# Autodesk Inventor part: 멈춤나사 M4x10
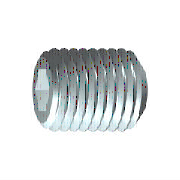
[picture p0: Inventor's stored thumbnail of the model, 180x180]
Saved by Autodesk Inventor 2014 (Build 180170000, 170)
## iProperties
Created: 2012-02
Part Number: 멈춤나사 M4x10
Material: 강철, 연강
Description: 6각 소켓 머리 없는 멈춤 나사
Document SubType Name: Modeling
Standard: KS B 1028
Designer: mduedu
Standards Organization: KS
Language: ko-KR
Size Designation: 납작점M4x10
Categories: <MemberInstance><Categories><Category DisplayName="조임쇠" InternalName="e4da775c-781d-43d5-af7c-5136215cf5a6" Mnemonic="FSTN"><Category DisplayName="볼트" InternalN
Density: 1 g/cm^3
Appearance: 강철
IsCustomPart: 1
Author: mduedu
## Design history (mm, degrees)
sketch "스케치1"
  geometry: L1 (0, 0)-(6.833, 0); L2 (10, 1.155)-(10, 2); L3 (10, 2)-(0, 2); L4 (10, 1.155)-(7.5, 1.155); L5 (7.5, 1.155)-(6.833, 0); L6 (0, -0.4)-(0, 2.4) reference; L7 (0, 2)-(0, 0)
  constraints: 13 end point, 3 parallel, 1 collinear, 1 perpendicular, 1 point on line
  dimensions: "d0" = 2.5 distance of L2.start L4.end (= INTI); "d1" = 60 deg angle of L5 L1; "d2" = 4 diameter of L3 L1 (= NND); "d3" = 2.3094 diameter of L4 L1 (= 1.1547 x SW); "d5" = 10 distance from line of L2 L3.end (= NLG)
revolve "본체" sketch "스케치1" stored, may be unused: angle "d6" = 90 deg
sketch "스케치2"
  geometry: L1 (-0.577, 1)-(0.577, 1); L2 (0.577, 1)-(1.155, 0); L3 (1.155, 0)-(0.577, -1); L4 (0.577, -1)-(-0.577, -1); L5 (-0.577, -1)-(-1.155, 0); L6 (-1.155, 0)-(-0.577, 1); A1 r 1.155 centre (0, 0) between (-0.577, 1) and (0.577, 1) reference; 2 further points
  constraints: 12 end point, 2 point on circle, 1 coincident, 1 horizontal, 11 other
extrude "슬롯" join sketch "스케치2" taper "d9" = 0 deg; stored distance "d21" = 10
workaxis "Work Axis1"
workplane "Work Plane1"
body "Solid1"
chamfer "모따기1" distance "d7" = 0.42941 (= -0.5 x GD1 + 0.5 x NND); stored, may be unused: angle "d8" = 45 deg (= FAWI), second distance "d29" = 0.42941 (= -0.5 x GD1 + 0.5 x NND)
feature "스레드" dims "d11" = 10 (= NLG), "d12" = 0
chamfer "모따기2" distance "d13" = 0.42941 (= -0.5 x GD1 + 0.5 x NND); stored, may be unused: angle "d14" = 45 deg (= FAWI), second distance "d30" = 0.42941 (= -0.5 x GD1 + 0.5 x NND)
other parameters: "NND" = 4 [user parameter; used in 5 equation terms], "NLG" = 10 [user parameter; used in 2 equation terms], "INTI" = 2.5 [user parameter; used in 1 equation term], "FAWI" = 45 deg [user parameter; used in 2 equation terms], "SW" = 2 [user parameter; used in 2 equation terms], "GD1" = 3.14117 (= THREADDIA - 1.2269 x PTC) [user parameter; used in 4 equation terms], "d4" = 0, "FAWI1" = 45 deg [user parameter], "d15" = 0, "d31" = 0, "GUL" = 0.42941 (= 0.61345 x PTC) [user parameter], "SPD" = 2.5 [user parameter], "TPU" = 14.28571 (computed from PTC) [user parameter], "TOA" = 30 deg [user parameter], "THREADDIA" = 4 [user parameter; used in 1 equation term], "PTC" = 0.7 [user parameter; used in 4 equation terms], "GAL" = 0.42941 (= 0.61345 x PTC) [user parameter], "E0" = 2.31 (= 1.155 x SW) [user parameter]
